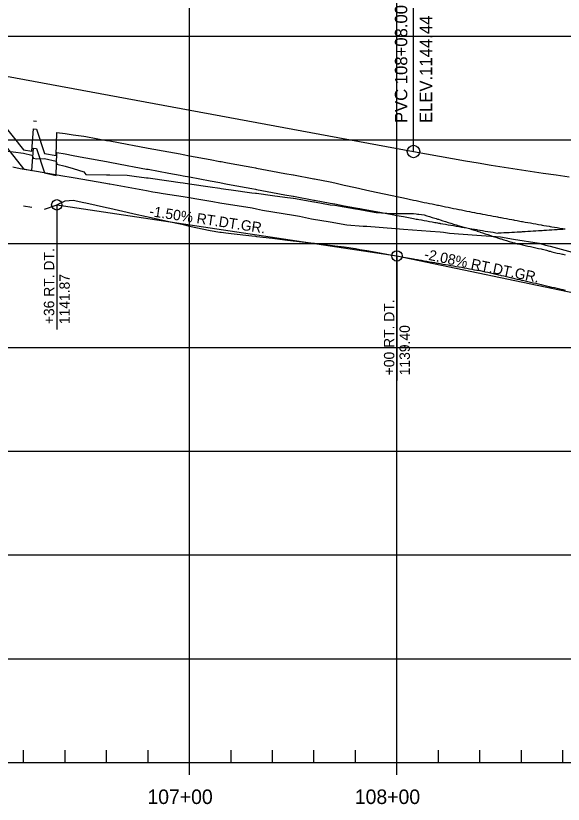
# Model space of a CAD drawing. Extents: x 688474 to 694748, y 765018 to 767373.
# Drawn here: x 691569.8 to 691833.8, y 765789.8 to 766169.7 of the extents above; entities that cross this region are included whole.
import ezdxf

# ---------------------------------------------------------------- set-up
doc = ezdxf.new("R2010")
doc.units = 0
for name, color, linetype in [('30', 7, 'Continuous'), ('37', 7, 'Continuous'), ('R_Exist Surface', 7, 'Continuous'), ('R_Profile Work Left', 7, 'Continuous'), ('R_Profile Work Right', 7, 'Continuous'), ('R_Vert Alg', 7, 'Continuous'), ('R_Vert Alg Annot', 7, 'Continuous')]:
    doc.layers.add(name, color=color, linetype=linetype)

msp = doc.modelspace()

# ---------------------------------------------------------------- linework, layer by layer
at = {"layer": '37'}
for p, q in [((691653.59, 765809.92), (691653.59, 766359.92)), ((691753.59, 765809.92), (691753.59, 766359.92)), ((690853.59, 766159.92), (693453.59, 766159.92)), ((690853.59, 766109.92), (693453.59, 766109.92)), ((690853.59, 766059.92), (693453.59, 766059.92)), ((690853.59, 766009.92), (693453.59, 766009.92)), ((690853.59, 765959.92), (693453.59, 765959.92)), ((690853.59, 765909.92), (693453.59, 765909.92)), ((690853.59, 765859.92), (693453.59, 765859.92)), ((691573.59, 765809.92), (691573.59, 765815.92)), ((691593.59, 765809.92), (691593.59, 765815.92)), ((691613.59, 765809.92), (691613.59, 765815.92)), ((691633.59, 765809.92), (691633.59, 765815.92)), ((691673.59, 765809.92), (691673.59, 765815.92)), ((691693.59, 765809.92), (691693.59, 765815.92)), ((691713.59, 765809.92), (691713.59, 765815.92)), ((691733.59, 765809.92), (691733.59, 765815.92)), ((691773.59, 765809.92), (691773.59, 765815.92)), ((691793.59, 765809.92), (691793.59, 765815.92)), ((691813.59, 765809.92), (691813.59, 765815.92)), ((691833.59, 765809.92), (691833.59, 765815.92)), ((690853.59, 765809.92), (693453.59, 765809.92)), ((691653.59, 765803.92), (691653.59, 765809.92)), ((691753.59, 765803.92), (691753.59, 765809.92))]:
    msp.add_line(p, q, dxfattribs=at)
at = {"layer": 'R_Exist Surface'}
msp.add_lwpolyline([(691568.31, 766096.85), (691571.98, 766096.17), (691579.77, 766094.85), (691590.7, 766092.95), (691591.51, 766092.82), (691597.47, 766091.79), (691613.22, 766089), (691614.86, 766088.74), (691615.16, 766088.68), (691632.86, 766085.47), (691635.84, 766084.92), (691638.15, 766084.54), (691640.92, 766084.03), (691650.56, 766082.55), (691660.98, 766080.92), (691664.86, 766080.17), (691668.26, 766079.63), (691683.79, 766077.11), (691685.96, 766076.67), (691688.7, 766076.11), (691703.66, 766073.61), (691706.61, 766073.11), (691712.4, 766071.87), (691721.35, 766070.34), (691729.42, 766068.94), (691737.38, 766068.37), (691739.05, 766068.25), (691752.83, 766067.25), (691756.75, 766066.95), (691769.77, 766065.93), (691774.45, 766065.57), (691776, 766065.45), (691778.95, 766065.02), (691792.15, 766064.04), (691798.85, 766063.52), (691799.37, 766063.44), (691803.59, 766063.15), (691809.85, 766062.11), (691822.16, 766060.09), (691825.3, 766059.25), (691827.54, 766058.65), (691845.24, 766053.87)], dxfattribs=at)
at = {"layer": 'R_Profile Work Left'}
for points in [[(691563.59, 766117.56), (691573.59, 766105.16), (691577.59, 766104.46), (691578.43, 766115.23), (691579.77, 766115.02), (691583.59, 766103.41), (691589.3, 766102.41), (691589.59, 766113.48), (691593.59, 766112.92), (691597.47, 766112.38), (691602.68, 766111.64), (691603.59, 766111.52), (691613.59, 766109.66), (691615.16, 766109.37), (691623.59, 766107.81), (691626.94, 766107.19), (691632.86, 766106.1), (691633.59, 766105.96), (691643.59, 766104.11), (691649, 766103.11), (691650.56, 766102.82), (691653.59, 766102.26), (691663.59, 766100.41), (691668.26, 766099.54), (691668.84, 766099.43), (691671.05, 766099.02), (691673.59, 766098.56), (691683.59, 766096.7), (691685.34, 766096.38), (691685.96, 766096.27), (691693.59, 766094.85), (691699.62, 766093.74), (691703.59, 766093), (691703.66, 766092.99), (691713.59, 766091.15), (691713.91, 766091.09), (691721.35, 766089.71), (691721.44, 766089.7), (691723.59, 766089.2), (691728.2, 766088.14), (691733.59, 766086.9), (691735.73, 766086.41), (691739.05, 766085.7), (691743.59, 766084.73), (691751.29, 766083.09), (691753.59, 766082.6), (691756.75, 766081.93), (691761.59, 766080.9), (691762.87, 766080.62), (691763.59, 766080.47), (691764.15, 766080.35), (691765.43, 766080.08), (691766.72, 766079.81), (691768, 766079.54), (691769.28, 766079.28), (691770.56, 766079.01), (691771.84, 766078.74), (691772.47, 766078.61), (691773.13, 766078.48), (691773.59, 766078.38), (691774.41, 766078.22), (691774.45, 766078.21), (691775.69, 766077.95), (691776.97, 766077.69), (691778.25, 766077.43), (691779.54, 766077.17), (691780.82, 766076.91), (691782.1, 766076.65), (691783.38, 766076.4), (691783.59, 766076.36), (691784.67, 766076.14), (691785.95, 766075.89), (691787.23, 766075.63), (691788.51, 766075.38), (691789.79, 766075.13), (691791.08, 766074.88), (691792.15, 766074.67), (691792.36, 766074.63), (691793.59, 766074.39), (691793.64, 766074.38), (691793.66, 766074.38), (691794.92, 766074.14), (691796.2, 766073.89), (691797.49, 766073.64), (691798.77, 766073.4), (691800.05, 766073.16), (691801.33, 766072.91), (691802.09, 766072.77), (691802.61, 766072.67), (691803.59, 766072.49), (691803.9, 766072.43), (691805.18, 766072.19), (691806.46, 766071.95), (691807.74, 766071.72), (691809.02, 766071.48), (691809.85, 766071.33), (691810.31, 766071.25), (691811.59, 766071.01), (691812.87, 766070.78), (691813.59, 766070.65), (691814.15, 766070.55), (691815.39, 766070.32), (691815.43, 766070.31), (691816.72, 766070.08), (691818, 766069.86), (691819.28, 766069.63), (691820.56, 766069.4), (691821.84, 766069.17), (691823.13, 766068.95), (691823.59, 766068.87), (691824.41, 766068.72), (691825.69, 766068.5), (691826.97, 766068.28), (691827.54, 766068.18), (691828.25, 766068.06), (691829.54, 766067.84), (691830.82, 766067.62), (691832.1, 766067.4), (691833.38, 766067.18), (691833.59, 766067.15), (691834.67, 766066.97)], [(691563.59, 766104.79), (691573.59, 766103.54), (691577.59, 766102.58), (691578.43, 766101.17), (691579.77, 766100.78), (691583.59, 766101), (691589.3, 766099.59), (691589.59, 766098.17), (691593.59, 766097.17), (691597.47, 766096.05), (691602.68, 766094.48), (691603.59, 766093.17), (691613.59, 766093.11), (691615.16, 766093.1), (691623.59, 766092.91), (691626.94, 766092.46), (691632.86, 766091.68), (691633.59, 766091.57), (691643.59, 766090.15), (691649, 766089.41), (691650.56, 766089.19), (691653.59, 766088.74), (691663.59, 766087.31), (691668.26, 766086.62), (691668.84, 766086.53), (691671.05, 766086.18), (691673.59, 766085.8), (691683.59, 766084.45), (691685.34, 766084.23), (691685.96, 766084.15), (691693.59, 766083.07), (691699.62, 766082.36), (691703.59, 766081.89), (691703.66, 766081.88), (691713.59, 766080.08), (691713.91, 766080.01), (691721.35, 766078.6), (691721.44, 766078.59), (691723.59, 766078.52), (691728.2, 766077.68), (691733.59, 766076.69), (691735.73, 766076.3), (691739.05, 766075.73), (691743.59, 766074.98), (691751.29, 766074.36), (691753.59, 766074.42), (691756.75, 766074.51), (691761.59, 766074.36), (691762.87, 766074.21), (691763.59, 766074.12), (691764.15, 766074.06), (691765.43, 766073.9), (691766.72, 766073.75), (691768, 766073.38), (691769.28, 766072.97), (691770.56, 766072.57), (691771.84, 766072.17), (691772.47, 766071.98), (691773.13, 766071.77), (691773.59, 766071.63), (691774.41, 766071.37), (691774.45, 766071.36), (691775.69, 766070.97), (691776.97, 766070.57), (691778.25, 766070.17), (691779.54, 766069.77), (691780.82, 766069.37), (691782.1, 766068.97), (691783.38, 766068.57), (691783.59, 766068.5), (691784.67, 766068.17), (691785.95, 766067.82), (691787.23, 766067.54), (691788.51, 766067.2), (691789.79, 766066.78), (691791.08, 766066.36), (691792.15, 766066.01), (691792.36, 766065.94), (691793.59, 766065.54), (691793.64, 766065.52), (691793.66, 766065.51), (691794.92, 766065.1), (691796.2, 766064.68), (691797.49, 766064.26), (691798.77, 766063.84), (691800.05, 766063.42), (691801.33, 766063), (691802.09, 766062.75), (691802.61, 766062.58), (691803.59, 766062.26), (691803.9, 766062.16), (691805.18, 766061.77), (691806.46, 766061.38), (691807.74, 766061), (691809.02, 766060.61), (691809.85, 766060.36), (691810.31, 766060.22), (691811.59, 766059.89), (691812.87, 766059.59), (691813.59, 766059.44), (691814.15, 766059.31), (691815.39, 766059.04), (691815.43, 766059.03), (691816.72, 766058.75), (691818, 766058.48), (691819.28, 766058.2), (691820.56, 766057.92), (691821.84, 766057.64), (691823.13, 766057.36), (691823.59, 766057.26), (691824.41, 766057.04), (691825.69, 766056.7), (691826.97, 766056.36), (691827.54, 766056.21), (691828.25, 766056.03), (691829.54, 766055.69), (691830.82, 766055.4), (691832.1, 766055.11), (691833.38, 766054.82), (691833.59, 766054.77), (691834.67, 766054.52)]]:
    msp.add_lwpolyline(points, dxfattribs=at)
at = {"layer": 'R_Profile Work Right'}
for points in [[(691578.43, 766119.07), (691579.77, 766118.84)], [(691563.59, 766108.68), (691573.59, 766096), (691577.59, 766095.19), (691578.43, 766105.93), (691579.77, 766105.69), (691583.59, 766093.97), (691589.3, 766092.81), (691589.59, 766103.87), (691593.59, 766103.13), (691597.47, 766102.41), (691602.68, 766101.44), (691603.59, 766101.28), (691613.59, 766099.42), (691615.16, 766099.13), (691623.59, 766097.57), (691626.94, 766096.95), (691632.86, 766095.86), (691633.59, 766095.72), (691643.59, 766093.87), (691649, 766092.87), (691650.56, 766092.58), (691653.59, 766092.02), (691663.59, 766090.17), (691668.26, 766089.3), (691668.84, 766089.19), (691671.05, 766088.78), (691673.59, 766088.32), (691683.59, 766086.46), (691685.34, 766086.14), (691685.96, 766086.03), (691693.59, 766084.61), (691699.62, 766083.5), (691703.59, 766082.76), (691703.66, 766082.75), (691713.59, 766080.91), (691713.91, 766080.85), (691721.35, 766079.47), (691721.44, 766079.46), (691723.59, 766079.06), (691728.2, 766078.2), (691733.59, 766077.21), (691735.73, 766076.81), (691739.05, 766076.19), (691743.59, 766075.35), (691751.29, 766073.93), (691753.59, 766073.5), (691756.75, 766072.92), (691761.59, 766072.02), (691762.87, 766071.78), (691763.59, 766071.65), (691764.15, 766071.55), (691765.43, 766071.31), (691766.72, 766071.08), (691768, 766070.85), (691769.28, 766070.62), (691770.56, 766070.38), (691771.84, 766070.16), (691772.47, 766070.04), (691773.13, 766069.93), (691773.59, 766069.84), (691774.41, 766069.7), (691774.45, 766069.69), (691775.69, 766069.47), (691776.97, 766069.25), (691778.25, 766069.02), (691779.54, 766068.8), (691780.82, 766068.58), (691782.1, 766068.35), (691783.38, 766068.13), (691783.59, 766068.1), (691784.67, 766067.91), (691785.95, 766067.69), (691787.23, 766067.48), (691788.51, 766067.26), (691789.79, 766067.04), (691791.08, 766066.83), (691792.15, 766066.65), (691792.36, 766066.62), (691793.59, 766066.41), (691793.64, 766066.4), (691793.66, 766066.4), (691794.92, 766066.19), (691796.2, 766065.98), (691797.49, 766065.77), (691798.77, 766065.56), (691800.05, 766065.36), (691801.33, 766065.15), (691802.09, 766065.03), (691802.61, 766065.06), (691803.59, 766065.11), (691803.9, 766065.13), (691805.18, 766065.2), (691806.46, 766065.27), (691807.74, 766065.34), (691809.02, 766065.41), (691809.85, 766065.46), (691810.31, 766065.49), (691811.59, 766065.56), (691812.87, 766065.64), (691813.59, 766065.68), (691814.15, 766065.71), (691815.39, 766065.79), (691815.43, 766065.79), (691816.72, 766065.86), (691818, 766065.94), (691819.28, 766066.02), (691820.56, 766066.1), (691821.84, 766066.18), (691823.13, 766066.26), (691823.59, 766066.29), (691824.41, 766066.34), (691825.69, 766066.42), (691826.97, 766066.51), (691827.54, 766066.54), (691828.25, 766066.59), (691829.54, 766066.67), (691830.82, 766066.76), (691832.1, 766066.85), (691833.38, 766066.93), (691833.59, 766066.95), (691834.67, 766067.02)], [(691573.59, 766078.1), (691577.59, 766077.49)], [(691583.59, 766076.47), (691589.3, 766078.41), (691589.59, 766078.61)], [(691589.59, 766078.61), (691593.59, 766080.61), (691597.47, 766080.86), (691602.68, 766079.7), (691603.59, 766079.5), (691613.59, 766077.28), (691615.16, 766076.93), (691623.59, 766075.06), (691626.94, 766074.31), (691632.86, 766073), (691633.59, 766072.84), (691643.59, 766070.62), (691649, 766069.42), (691650.56, 766069.07), (691653.59, 766068.4), (691663.59, 766066.18), (691668.26, 766065.48), (691668.84, 766065.41), (691671.05, 766065.15), (691673.59, 766064.85), (691683.59, 766063.67), (691685.34, 766063.46), (691685.96, 766063.39), (691693.59, 766062.48), (691699.62, 766061.77), (691703.59, 766061.3), (691703.66, 766061.29), (691713.59, 766060.11), (691713.91, 766060.07), (691721.35, 766059.19), (691721.44, 766059.18), (691723.59, 766058.93), (691728.2, 766058.38), (691733.59, 766057.49), (691735.73, 766057.11), (691739.05, 766056.53), (691743.59, 766055.73), (691751.29, 766054.37), (691753.59, 766053.97), (691756.75, 766053.41), (691761.59, 766052.56), (691762.87, 766052.34), (691763.59, 766052.21), (691764.15, 766052.11), (691765.43, 766051.88), (691766.72, 766051.66), (691768, 766051.43), (691769.28, 766051.21), (691770.56, 766050.98), (691771.84, 766050.76), (691772.47, 766050.65), (691773.13, 766050.53), (691773.59, 766050.45), (691774.41, 766050.3), (691774.45, 766050.3), (691775.69, 766050.08), (691776.97, 766049.85), (691778.25, 766049.63), (691779.54, 766049.4), (691780.82, 766049.18), (691782.1, 766048.95), (691783.38, 766048.73), (691783.59, 766048.69), (691784.67, 766048.5), (691785.95, 766048.27), (691787.23, 766048.05), (691788.51, 766047.82), (691789.79, 766047.6), (691791.08, 766047.37), (691792.15, 766047.18), (691792.36, 766047.15), (691793.59, 766046.93), (691793.64, 766046.92), (691793.66, 766046.92), (691794.92, 766046.69), (691796.2, 766046.39), (691797.49, 766046.1), (691798.77, 766045.8), (691800.05, 766045.51), (691801.33, 766045.21), (691802.09, 766045.04), (691802.61, 766044.92), (691803.59, 766044.69), (691803.9, 766044.62), (691805.18, 766044.33), (691806.46, 766044.03), (691807.74, 766043.74), (691809.02, 766043.44), (691809.85, 766043.25), (691810.31, 766043.15), (691811.59, 766042.85), (691812.87, 766042.56), (691813.59, 766042.39), (691814.15, 766042.26), (691815.39, 766041.98), (691815.43, 766041.97), (691816.72, 766041.67), (691818, 766041.38), (691819.28, 766041.08), (691820.56, 766040.79), (691821.84, 766040.49), (691823.13, 766040.2), (691823.59, 766040.09), (691824.41, 766039.91), (691825.69, 766039.61), (691826.97, 766039.32), (691827.54, 766039.18), (691828.25, 766039.02), (691829.54, 766038.73), (691830.82, 766038.43), (691832.1, 766038.14), (691833.38, 766037.84), (691833.59, 766037.79), (691834.67, 766037.55)]]:
    msp.add_lwpolyline(points, dxfattribs=at)
at = {"layer": 'R_Vert Alg'}
for p, q in [((691053.59, 766235.38), (691761.59, 766104.29)), ((691589.59, 766078.61), (691753.59, 766053.97)), ((691753.59, 766053.97), (691853.59, 766033.15))]:
    msp.add_line(p, q, dxfattribs=at)
msp.add_lwpolyline([(691761.59, 766104.29), (691767.84, 766103.15), (691774.09, 766102.03), (691780.34, 766100.93), (691786.59, 766099.86), (691792.84, 766098.81), (691799.09, 766097.78), (691805.34, 766096.78), (691811.59, 766095.81), (691817.84, 766094.85), (691824.09, 766093.93), (691830.34, 766093.02), (691836.59, 766092.14)], dxfattribs=at)
for centre, radius in [((691761.59, 766104.29), 3), ((691589.59, 766078.61), 2.5), ((691753.59, 766053.97), 2.5)]:
    msp.add_circle(centre, radius, dxfattribs=at)
at = {"layer": 'R_Vert Alg Annot'}
for p, q in [((691761.59, 766104.29), (691761.59, 766197.28)), ((691589.59, 766078.61), (691589.59, 766018.61)), ((691753.59, 766053.97), (691753.59, 765993.97))]:
    msp.add_line(p, q, dxfattribs=at)

# ---------------------------------------------------------------- texts
at = {"layer": '30'}
for s, p in [('107+00', (691633.28, 765789.92)), ('108+00', (691733.28, 765789.92))]:
    msp.add_text(s, height=7, dxfattribs=at).set_placement(p)
at = {"layer": 'R_Vert Alg Annot'}
for s, height, rotation, p in [('PVC 108+08.00', 6, 90, (691758.59, 766118)), ('ELEV.1144.44', 6, 90, (691770.59, 766118)), ('-1.50% RT.DT.GR.', 5, 351.4554, (691633.95, 766073.21)), ('+36 RT. DT.', 5, 90, (691588.34, 766021.11)), ('-2.08% RT.DT.GR.', 5, 348.2417, (691766.4, 766052.58)), ('1141.87', 5, 90, (691595.84, 766021.11)), ('+00 RT. DT.', 5, 90, (691752.34, 765996.47)), ('1139.40', 5, 90, (691759.84, 765996.47))]:
    msp.add_text(s, height=height, rotation=rotation, dxfattribs=at).set_placement(p)

doc.saveas('drawing.dxf')
